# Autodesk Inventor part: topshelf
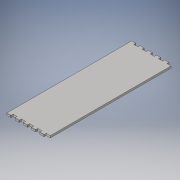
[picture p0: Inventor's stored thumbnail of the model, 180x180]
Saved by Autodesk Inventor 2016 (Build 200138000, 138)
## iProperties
Created: 2017-03
Part Number: topshelf
Material: Generic
Document SubType Name: Modeling
Designer: Corey
Density: 1 g/cm^3
Appearance: Default
Author: Corey
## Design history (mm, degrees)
sketch "Sketch1"
  geometry: L1 (0, 0)-(368.3, 0); L2 (368.3, 0)-(368.3, -1117.6); L3 (368.3, -1117.6)-(0, -1117.6); L4 (0, -1117.6)-(0, 0)
  constraints: 8 end point, 2 parallel, 1 horizontal, 1 perpendicular
  dimensions: "d0" = 368.3 distance of L2.end L3.end (= panel); "d1" = 1117.6 distance of L1.end L2.end (= width)
extrude "body" new body sketch "Sketch1" distance "d2" = 18.034 (= thick); taper "d3" = 0 deg
sketch "Sketch2"
  geometry: L1 (-368.3, 0)-(0, 0) reference; L2 (0, 0)-(-36.83, 0); L3 (-36.83, 0)-(-36.83, 21.209); L4 (-36.83, 21.209)-(0, 21.209); L5 (0, 21.209)-(0, 0); L6 (0, 0)-(0, 1117.6) reference; L7 (0, 558.8)-(-368.3, 558.8); L8 (-368.3, 1117.6)-(-368.3, 0) reference; L9 (0, 1117.6)-(-36.83, 1117.6); L10 (-36.83, 1117.6)-(-36.83, 1096.391); L11 (-36.83, 1096.391)-(0, 1096.391); L12 (0, 1096.391)-(0, 1117.6)
  constraints: 18 end point, 3 symmetric about line, 2 midpoint, 2 parallel, 1 horizontal, 1 perpendicular
  dimensions: "d4" = 36.83 distance of L3.end L4.end (= 0.1 x panel); "d5" = 21.209 distance of L2.end L3.end (= thick + 0.5 x bit)
extrude "sidetab" cut sketch "Sketch2" stored distance "d6" = 18.034 (= thick); taper "d7" = 0 deg
pattern_linear "sidetabP" dims "d10" = 73.66 (= 0.2 x panel)
chamfer "type2pressfit" distance "d11" = 2.25425 (= 0.125 x thick); stored, may be unused: second distance "d12" = 3.175, angle "d13" = 45 deg
body "Solid1"
other parameters: "height" = 1917.7 [user parameter], "width" = 1117.6 [user parameter; used in 1 equation term], "depth" = 425.45 [user parameter], "thick" = 18.034 [user parameter; used in 4 equation terms], "bit" = 6.35 [user parameter; used in 1 equation term], "top" = 152.4 [user parameter], "panel" = 368.3 [user parameter; used in 3 equation terms], "sweater" = 330.2 [user parameter], "shoe" = 152.4 [user parameter], "osb" = 19.05 [user parameter]
